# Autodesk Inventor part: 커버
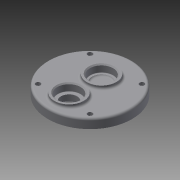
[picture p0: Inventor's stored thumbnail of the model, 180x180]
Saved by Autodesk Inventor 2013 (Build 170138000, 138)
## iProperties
Created: 2015-07
Part Number: 커버
Material: 일반
Document SubType Name: Modeling
Designer: user
Density: 1 g/cm^3
Author: user
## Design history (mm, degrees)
sketch "스케치1"
  geometry: C1 r 40 at (0, 0); 1 further point
  constraints: 1 centre point, 1 coincident
  dimensions: "d0" = 80 diameter of C1
extrude "돌출1" new body sketch "스케치1" distance "d1" = 9; taper "d2" = 0 deg
sketch "스케치2"
  geometry: L1 (0, 0)-(0, 11); C1 r 40 at (0, 0) reference; C2 r 14 at (0, 11)
  constraints: 2 end point, 1 centre point, 1 coincident, 1 vertical
  dimensions: "d3" = 11 distance of L1.start L1.end; "d4" = 28 diameter of C2
extrude "돌출2" join sketch "스케치2" distance "d5" = 3; taper "d6" = 0 deg
sketch "스케치3"
  geometry: L1 (0, 0)-(0, -20); C1 r 40 at (0, 0) reference; C2 r 14 at (0, -20)
  constraints: 2 end point, 1 centre point, 1 coincident, 1 vertical
  dimensions: "d7" = 20 distance of L1.start L1.end; "d8" = 28 diameter of C2
extrude "돌출3" join sketch "스케치3" distance "d9" = 3; taper "d10" = 0 deg
sketch "스케치4"
  geometry: L1 (0, 0)-(0, -20); C1 r 40 at (0, 0) reference; C2 r 15 at (0, -20)
  constraints: 2 end point, 1 centre point, 1 coincident, 1 vertical
  dimensions: "d11" = 20 distance of L1.start L1.end; "d12" = 30 diameter of C2
extrude "돌출4" join sketch "스케치4" distance "d13" = 4; taper "d14" = 0 deg
hole "구멍1" diameter "d17" = 15; stored, may be unused: countersink angle "d21" = 90 deg, drill point angle "d23" = 118 deg; dims "d15" = 10, "d16" = 10, "d18" = 6, "d19" = 22, "d20" = 7, "d22" = 8
hole "구멍2" diameter "d26" = 22; stored, may be unused: countersink angle "d30" = 90 deg, drill point angle "d32" = 118 deg; dims "d24" = 10, "d25" = 10, "d27" = 6, "d28" = 22, "d29" = 7, "d31" = 7
hole "구멍3" diameter "d35" = 18; stored, may be unused: countersink angle "d39" = 90 deg, drill point angle "d41" = 0 deg; dims "d33" = 10, "d34" = 10, "d36" = 6, "d37" = 22, "d38" = 7, "d40" = 8
fillet "모깎기1" dims "d42" = 2
fillet "모깎기2" dims "d43" = 0.3
chamfer "모따기1" distance "d44" = 1; stored, may be unused: second distance "d45" = 2, angle "d46" = 45 deg
fillet "모깎기3" dims "d47" = 0.3
fillet "모깎기4" dims "d48" = 2
sketch "스케치6"
  geometry: L1 (0, 0)-(24.749, 24.749); L2 (0, 0)-(35, 0); C1 r 40 at (0, 0) reference
  constraints: 4 end point, 1 equal length, 1 horizontal
  dimensions: "d51" = 35 distance of L1.start L1.end; "d52" = 45 deg angle of L2 L1
hole "구멍4" sketch "스케치6" at (24.749, 24.749) diameter "d53" = 4.5; stored, may be unused: countersink angle "d57" = 90 deg, drill point angle "d59" = 0 deg; dims "d54" = 6, "d55" = 8, "d56" = 4.4, "d58" = 8
fillet "모깎기5" dims "d63" = 2
node "솔리드1"
pattern_circular "원형 패턴1" dims angle "d61" = 360 deg
